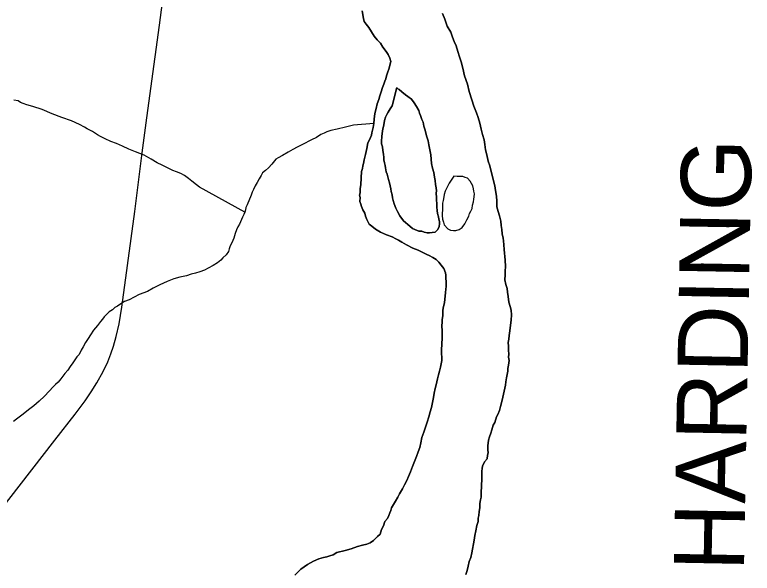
# Model space of a CAD drawing. Extents: x 0 to 34, y 0 to 22.
# Drawn here: x 25.659 to 26.257, y 15.442 to 15.894 of the extents above; entities that cross this region are included whole.
import ezdxf

# ---------------------------------------------------------------- set-up
doc = ezdxf.new("R2010")
doc.units = 0
for name, color, linetype in [('GM_X_County_Road_Text', 7, 'Continuous'), ('GM_X_Major_River', 7, 'Continuous'), ('GM_X_Minor_River', 7, 'Continuous'), ('GM_X_State_Route', 7, 'Continuous')]:
    doc.layers.add(name, color=color, linetype=linetype)

msp = doc.modelspace()

# ---------------------------------------------------------------- linework, layer by layer
at = {"layer": 'GM_X_Major_River'}
for points in [[(25.94104, 15.8974), (25.94199, 15.89128), (25.94266, 15.88859), (25.94413, 15.88664), (25.94632, 15.88391), (25.9485, 15.88041), (25.95067, 15.87691), (25.95324, 15.87379), (25.95581, 15.87104), (25.95762, 15.86794), (25.96055, 15.86441), (25.962, 15.86208), (25.96343, 15.85899), (25.9641, 15.85631), (25.96366, 15.85442), (25.96279, 15.85102), (25.96153, 15.84726), (25.96068, 15.84463), (25.96023, 15.84236), (25.95941, 15.84048), (25.95856, 15.83785), (25.95734, 15.83522), (25.95646, 15.83183), (25.95521, 15.82845), (25.95435, 15.82543), (25.9531, 15.82205), (25.95222, 15.81827), (25.95133, 15.81412), (25.9508, 15.80957), (25.95031, 15.80616), (25.94982, 15.80275), (25.94893, 15.79859), (25.94849, 15.79671), (25.94685, 15.79296), (25.94562, 15.79033), (25.94471, 15.7858), (25.94379, 15.78088), (25.94252, 15.77674), (25.94204, 15.77371), (25.9416, 15.77182), (25.94115, 15.76956), (25.94031, 15.7673), (25.93997, 15.75666), (25.93948, 15.75325), (25.93937, 15.74983), (25.93893, 15.74794), (25.93925, 15.74603), (25.93916, 15.74299), (25.93984, 15.74068), (25.94054, 15.73876), (25.9416, 15.73606), (25.94304, 15.73335), (25.94372, 15.73104), (25.94478, 15.72834), (25.94656, 15.72448), (25.9488, 15.72289), (25.95177, 15.7205), (25.95588, 15.71809), (25.96076, 15.71602), (25.96528, 15.71435), (25.96828, 15.71273), (25.97052, 15.71152), (25.97314, 15.70991), (25.97688, 15.70788), (25.98212, 15.70505), (25.98626, 15.70339), (25.99001, 15.70174), (25.99339, 15.70011), (25.99527, 15.69928)], [(25.99527, 15.69928), (25.99339, 15.70011), (25.99001, 15.70174), (25.98626, 15.70339), (25.98212, 15.70505), (25.97688, 15.70788), (25.97314, 15.70991), (25.97052, 15.71152), (25.96828, 15.71273), (25.96528, 15.71435), (25.96076, 15.71602), (25.95588, 15.71809), (25.95177, 15.7205), (25.9488, 15.72289), (25.94656, 15.72448), (25.94478, 15.72834), (25.94372, 15.73104), (25.94304, 15.73335), (25.9416, 15.73606), (25.94054, 15.73876), (25.93984, 15.74068), (25.93916, 15.74299), (25.93925, 15.74603), (25.93893, 15.74794), (25.93937, 15.74983), (25.93948, 15.75325), (25.93997, 15.75666), (25.94031, 15.7673), (25.94115, 15.76956), (25.9416, 15.77182), (25.94204, 15.77371), (25.94252, 15.77674), (25.94379, 15.78088), (25.94471, 15.7858), (25.94562, 15.79033), (25.94685, 15.79296), (25.94849, 15.79671), (25.94893, 15.79859), (25.94982, 15.80275), (25.95031, 15.80616), (25.9508, 15.80957), (25.95133, 15.81412), (25.95222, 15.81827), (25.9531, 15.82205), (25.95435, 15.82543), (25.95521, 15.82845), (25.95646, 15.83183), (25.95734, 15.83522), (25.95856, 15.83785), (25.95941, 15.84048), (25.96023, 15.84236), (25.96068, 15.84463), (25.96153, 15.84726), (25.96279, 15.85102), (25.96366, 15.85442), (25.9641, 15.85631), (25.96343, 15.85899), (25.962, 15.86208), (25.96055, 15.86441), (25.95762, 15.86794), (25.95581, 15.87104), (25.95324, 15.87379), (25.95067, 15.87691), (25.9485, 15.88041), (25.94632, 15.88391), (25.94413, 15.88664), (25.94266, 15.88859), (25.94199, 15.89128), (25.94104, 15.8974)], [(26.04543, 15.76725), (26.04443, 15.77185), (26.04303, 15.7757), (26.04205, 15.78068), (26.04104, 15.7849), (26.04041, 15.78911), (26.03977, 15.79293), (26.03838, 15.79716), (26.03738, 15.80138), (26.03639, 15.80636), (26.03502, 15.81097), (26.03361, 15.81482), (26.0315, 15.82022), (26.02976, 15.82522), (26.02769, 15.83214), (26.02635, 15.83789), (26.02391, 15.84482), (26.02258, 15.85095), (26.02122, 15.85594), (26.01983, 15.86017), (26.01844, 15.86441), (26.01707, 15.86902), (26.01565, 15.87248), (26.01424, 15.87596), (26.01285, 15.88019), (26.00995, 15.88485), (26.00785, 15.89063), (26.0061, 15.89525)], [(26.0061, 15.89525), (26.00785, 15.89063), (26.00995, 15.88485), (26.01285, 15.88019), (26.01424, 15.87596), (26.01565, 15.87248), (26.01707, 15.86902), (26.01844, 15.86441), (26.01983, 15.86017), (26.02122, 15.85594), (26.02258, 15.85095), (26.02391, 15.84482), (26.02635, 15.83789), (26.02769, 15.83214), (26.02976, 15.82522), (26.0315, 15.82022), (26.03361, 15.81482), (26.03502, 15.81097), (26.03639, 15.80636), (26.03738, 15.80138), (26.03838, 15.79716), (26.03977, 15.79293), (26.04041, 15.78911), (26.04104, 15.7849), (26.04205, 15.78068), (26.04303, 15.7757), (26.04443, 15.77185), (26.04543, 15.76725)], [(25.96914, 15.83521), (25.96524, 15.8205), (25.96364, 15.81789), (25.96203, 15.81528), (25.96083, 15.81342), (25.96, 15.81116), (25.95915, 15.80853), (25.95871, 15.80664), (25.95823, 15.80361), (25.95779, 15.80173), (25.95729, 15.79794), (25.95683, 15.79567), (25.95671, 15.79187), (25.95664, 15.78959), (25.95733, 15.78728), (25.95761, 15.78423), (25.95828, 15.78116), (25.95857, 15.77849), (25.95851, 15.77659), (25.9592, 15.77429), (25.9595, 15.77199), (25.95982, 15.77008), (25.96049, 15.76702), (25.96119, 15.76509), (25.96188, 15.76278), (25.9622, 15.76087), (25.96325, 15.75817), (25.96355, 15.7555), (25.96424, 15.7532), (25.96454, 15.7509), (25.96522, 15.74821), (25.96553, 15.74592), (25.96621, 15.74362), (25.96689, 15.74093), (25.9683, 15.73746), (25.96974, 15.73475), (25.97153, 15.73127), (25.97446, 15.72737), (25.97965, 15.72301), (25.98187, 15.72103), (25.98375, 15.72021), (25.98676, 15.71897), (25.98942, 15.71888), (25.9913, 15.71806), (25.99357, 15.7176), (25.99547, 15.71754)], [(25.96914, 15.83521), (25.96913, 15.83483), (25.971, 15.83363), (25.97322, 15.83165), (25.97619, 15.82927), (25.97805, 15.82807), (25.98102, 15.82569), (25.98322, 15.82295), (25.98503, 15.81985), (25.98683, 15.81675), (25.98752, 15.81444), (25.98822, 15.81252), (25.98927, 15.80944), (25.99033, 15.80712), (25.991, 15.80406), (25.99203, 15.80059), (25.99302, 15.796), (25.99443, 15.79215), (25.99508, 15.7887), (25.99672, 15.78066), (25.997, 15.77722), (25.99727, 15.77379), (25.99791, 15.76997), (25.99894, 15.76651), (25.99958, 15.76268), (26.00025, 15.75999), (26.00053, 15.75656), (26.00082, 15.75389), (26.00113, 15.75159), (26.00107, 15.7497), (26.00134, 15.74626), (26.00125, 15.7436), (26.00157, 15.74169), (26.00146, 15.73827), (26.00176, 15.73559), (26.00207, 15.7333), (26.00274, 15.73062), (26.00306, 15.7287), (26.00376, 15.72678), (26.0037, 15.72488), (26.00325, 15.72261), (26.00241, 15.72035), (26.00006, 15.71815), (25.99776, 15.71784), (25.99547, 15.71754), (25.99357, 15.7176), (25.9913, 15.71806), (25.98942, 15.71888), (25.98676, 15.71897), (25.98375, 15.72021), (25.98187, 15.72103), (25.97965, 15.72301), (25.97446, 15.72737), (25.97153, 15.73127), (25.96974, 15.73475), (25.9683, 15.73746), (25.96689, 15.74093), (25.96621, 15.74362), (25.96553, 15.74592), (25.96522, 15.74821), (25.96454, 15.7509), (25.96424, 15.7532), (25.96355, 15.7555), (25.96325, 15.75817), (25.9622, 15.76087), (25.96188, 15.76278), (25.96119, 15.76509), (25.96049, 15.76702), (25.95982, 15.77008), (25.9595, 15.77199), (25.9592, 15.77429), (25.95851, 15.77659), (25.95857, 15.77849), (25.95828, 15.78116), (25.95761, 15.78423), (25.95733, 15.78728), (25.95664, 15.78959), (25.95671, 15.79187), (25.95683, 15.79567), (25.95729, 15.79794), (25.95779, 15.80173), (25.95823, 15.80361), (25.95871, 15.80664), (25.95915, 15.80853), (25.96, 15.81116), (25.96083, 15.81342), (25.96203, 15.81528), (25.96364, 15.81789), (25.96524, 15.8205), (25.96914, 15.83521)], [(25.99547, 15.71754), (25.99776, 15.71784), (26.00006, 15.71815), (26.00241, 15.72035), (26.00325, 15.72261), (26.0037, 15.72488), (26.00376, 15.72678), (26.00306, 15.7287), (26.00274, 15.73062), (26.00207, 15.7333), (26.00176, 15.73559), (26.00146, 15.73827), (26.00157, 15.74169), (26.00125, 15.7436), (26.00134, 15.74626), (26.00107, 15.7497), (26.00113, 15.75159), (26.00082, 15.75389), (26.00053, 15.75656), (26.00025, 15.75999), (25.99958, 15.76268), (25.99894, 15.76651), (25.99791, 15.76997), (25.99727, 15.77379), (25.997, 15.77722), (25.99672, 15.78066), (25.99508, 15.7887), (25.99443, 15.79215), (25.99302, 15.796), (25.99203, 15.80059), (25.991, 15.80406), (25.99033, 15.80712), (25.98927, 15.80944), (25.98822, 15.81252), (25.98752, 15.81444), (25.98683, 15.81675), (25.98503, 15.81985), (25.98322, 15.82295), (25.98102, 15.82569), (25.97805, 15.82807), (25.97619, 15.82927), (25.97322, 15.83165), (25.971, 15.83363), (25.96913, 15.83483), (25.96914, 15.83521)], [(26.02509, 15.44072), (26.02596, 15.44412), (26.02684, 15.44751), (26.02772, 15.45129), (26.02897, 15.45467), (26.02985, 15.45845), (26.0317, 15.46866), (26.0322, 15.47245), (26.03308, 15.47622), (26.03398, 15.48038), (26.03485, 15.48377), (26.03493, 15.48643), (26.03539, 15.4887), (26.03586, 15.49173), (26.03634, 15.49476), (26.03645, 15.49818), (26.03693, 15.50121), (26.03738, 15.50347), (26.03746, 15.50575), (26.03753, 15.50803), (26.03764, 15.51145), (26.03772, 15.51411), (26.03781, 15.51677), (26.03789, 15.51944), (26.03798, 15.5221), (26.03805, 15.52438), (26.03812, 15.52666), (26.03856, 15.52854), (26.04019, 15.53191), (26.04218, 15.53451), (26.04266, 15.53754), (26.0431, 15.53943), (26.04279, 15.54172), (26.0429, 15.54514), (26.04296, 15.54704), (26.04343, 15.54969), (26.04427, 15.55233), (26.04513, 15.55534), (26.04598, 15.55798), (26.04724, 15.56174), (26.04845, 15.56398), (26.04974, 15.56851), (26.05094, 15.57037), (26.05219, 15.57375), (26.05305, 15.57677), (26.05391, 15.57978), (26.05482, 15.58432), (26.05703, 15.59414), (26.0575, 15.59678), (26.05799, 15.60019), (26.05846, 15.60284), (26.05892, 15.60549), (26.05899, 15.60777), (26.05946, 15.61042), (26.05996, 15.6142), (26.05967, 15.61688), (26.05974, 15.61916), (26.05947, 15.62259), (26.05956, 15.62563), (26.05928, 15.62868), (26.05975, 15.63133), (26.06022, 15.63436), (26.06073, 15.63815), (26.06125, 15.6427), (26.06176, 15.64687), (26.0619, 15.65105), (26.06164, 15.65486), (26.06098, 15.65793), (26.05994, 15.66138), (26.05933, 15.66597), (26.05868, 15.66941), (26.05839, 15.67247), (26.05735, 15.67555), (26.05671, 15.67937), (26.05684, 15.68355), (26.05694, 15.68659), (26.05706, 15.69039), (26.05684, 15.69535), (26.05656, 15.6984), (26.05626, 15.70107), (26.05598, 15.70413), (26.05572, 15.70794), (26.05543, 15.71099), (26.05513, 15.71329), (26.05448, 15.71673), (26.05421, 15.72017), (26.05355, 15.72361), (26.05328, 15.72705), (26.05228, 15.73126), (26.05124, 15.73472), (26.05022, 15.73856), (26.04999, 15.74313), (26.04974, 15.74733), (26.04913, 15.75191), (26.04849, 15.75574), (26.04543, 15.76725)], [(26.04543, 15.76725), (26.04849, 15.75574), (26.04913, 15.75191), (26.04974, 15.74733), (26.04999, 15.74313), (26.05022, 15.73856), (26.05124, 15.73472), (26.05228, 15.73126), (26.05328, 15.72705), (26.05355, 15.72361), (26.05421, 15.72017), (26.05448, 15.71673), (26.05513, 15.71329), (26.05543, 15.71099), (26.05572, 15.70794), (26.05598, 15.70413), (26.05626, 15.70107), (26.05656, 15.6984), (26.05684, 15.69535), (26.05706, 15.69039), (26.05694, 15.68659), (26.05684, 15.68355), (26.05671, 15.67937), (26.05735, 15.67555), (26.05839, 15.67247), (26.05868, 15.66941), (26.05933, 15.66597), (26.05994, 15.66138), (26.06098, 15.65793), (26.06164, 15.65486), (26.0619, 15.65105), (26.06176, 15.64687), (26.06125, 15.6427), (26.06073, 15.63815), (26.06022, 15.63436), (26.05975, 15.63133), (26.05928, 15.62868), (26.05956, 15.62563), (26.05947, 15.62259), (26.05974, 15.61916), (26.05967, 15.61688), (26.05996, 15.6142), (26.05946, 15.61042), (26.05899, 15.60777), (26.05892, 15.60549), (26.05846, 15.60284), (26.05799, 15.60019), (26.0575, 15.59678), (26.05703, 15.59414), (26.05482, 15.58432), (26.05391, 15.57978), (26.05305, 15.57677), (26.05219, 15.57375), (26.05094, 15.57037), (26.04974, 15.56851), (26.04845, 15.56398), (26.04724, 15.56174), (26.04598, 15.55798), (26.04513, 15.55534), (26.04427, 15.55233), (26.04343, 15.54969), (26.04296, 15.54704), (26.0429, 15.54514), (26.04279, 15.54172), (26.0431, 15.53943), (26.04266, 15.53754), (26.04218, 15.53451), (26.04019, 15.53191), (26.03856, 15.52854), (26.03812, 15.52666), (26.03805, 15.52438), (26.03798, 15.5221), (26.03789, 15.51944), (26.03781, 15.51677), (26.03772, 15.51411), (26.03764, 15.51145), (26.03753, 15.50803), (26.03746, 15.50575), (26.03738, 15.50347), (26.03693, 15.50121), (26.03645, 15.49818), (26.03634, 15.49476), (26.03586, 15.49173), (26.03539, 15.4887), (26.03493, 15.48643), (26.03485, 15.48377), (26.03398, 15.48038), (26.03308, 15.47622), (26.0322, 15.47245), (26.0317, 15.46866), (26.02985, 15.45845), (26.02897, 15.45467), (26.02772, 15.45129), (26.02684, 15.44751), (26.02596, 15.44412), (26.02509, 15.44072)], [(26.02206, 15.76308), (26.02016, 15.76314), (26.01787, 15.76322), (26.01521, 15.76331), (26.01362, 15.76108), (26.0116, 15.75772), (26.00958, 15.75398), (26.00836, 15.75136), (26.00751, 15.74872), (26.00707, 15.74683), (26.00659, 15.74381), (26.00614, 15.74154), (26.00602, 15.73774), (26.00596, 15.73584), (26.00588, 15.73356), (26.00582, 15.73166), (26.00611, 15.7286), (26.00679, 15.7263), (26.00748, 15.72399), (26.01043, 15.72085), (26.01268, 15.71963), (26.01496, 15.71956)], [(26.02206, 15.76308), (26.02016, 15.76314), (26.01787, 15.76322), (26.01521, 15.76331), (26.01362, 15.76108), (26.0116, 15.75772), (26.00958, 15.75398), (26.00836, 15.75136), (26.00751, 15.74872), (26.00707, 15.74683), (26.00659, 15.74381), (26.00614, 15.74154), (26.00602, 15.73774), (26.00596, 15.73584), (26.00588, 15.73356), (26.00582, 15.73166), (26.00611, 15.7286), (26.00679, 15.7263), (26.00748, 15.72399), (26.01043, 15.72085), (26.01268, 15.71963), (26.01496, 15.71956), (26.01686, 15.7195), (26.01955, 15.72017), (26.02189, 15.72199), (26.02427, 15.72496), (26.02589, 15.72795), (26.02751, 15.73094), (26.02796, 15.73321), (26.02916, 15.73507), (26.03, 15.73733), (26.03046, 15.73997), (26.03131, 15.74261), (26.03138, 15.74489), (26.03182, 15.74678), (26.03189, 15.74906), (26.03159, 15.75135), (26.03127, 15.75326), (26.03058, 15.75557), (26.02842, 15.75945), (26.02621, 15.7618), (26.02432, 15.76224), (26.02244, 15.76307), (26.02206, 15.76308)], [(26.01496, 15.71956), (26.01686, 15.7195), (26.01955, 15.72017), (26.02189, 15.72199), (26.02427, 15.72496), (26.02589, 15.72795), (26.02751, 15.73094), (26.02796, 15.73321), (26.02916, 15.73507), (26.03, 15.73733), (26.03046, 15.73997), (26.03131, 15.74261), (26.03138, 15.74489), (26.03182, 15.74678), (26.03189, 15.74906), (26.03159, 15.75135), (26.03127, 15.75326), (26.03058, 15.75557), (26.02842, 15.75945), (26.02621, 15.7618), (26.02432, 15.76224), (26.02244, 15.76307), (26.02206, 15.76308)], [(25.99527, 15.69928), (25.99826, 15.69766), (26.00088, 15.69606), (26.00309, 15.6937), (26.00492, 15.69136), (26.00711, 15.68862), (26.00853, 15.68515), (26.00885, 15.68323), (26.00875, 15.6802), (26.00907, 15.67828), (26.00901, 15.67638), (26.00893, 15.6741), (26.00886, 15.67182), (26.0084, 15.66917), (26.00775, 15.66082), (26.00689, 15.65781), (26.00641, 15.65478), (26.00634, 15.6525), (26.00628, 15.6506), (26.00579, 15.64719), (26.00573, 15.64529), (26.00563, 15.64225), (26.00588, 15.63806), (26.0057, 15.63236), (26.00554, 15.62742), (26.00539, 15.62285), (26.00528, 15.61943), (26.00558, 15.61676), (26.0055, 15.6141), (26.00503, 15.61145), (26.00457, 15.60881), (26.00369, 15.60541), (26.00284, 15.60239), (26.00198, 15.59938), (26.00106, 15.59446), (26.0002, 15.59145), (25.99932, 15.58767), (25.99883, 15.58426), (25.99794, 15.58011), (25.99704, 15.57595), (25.99617, 15.57256), (25.9949, 15.56841), (25.99362, 15.56427), (25.99235, 15.56013), (25.99107, 15.55598), (25.98942, 15.55185), (25.98851, 15.54732), (25.98763, 15.54354), (25.98638, 15.54016), (25.98511, 15.5364), (25.98346, 15.53227), (25.9818, 15.52814), (25.98015, 15.52401), (25.9785, 15.52026), (25.97725, 15.51687), (25.97524, 15.51352), (25.97361, 15.51014), (25.9712, 15.50604), (25.96997, 15.50342), (25.96796, 15.50006), (25.96475, 15.49484), (25.96429, 15.49257), (25.96347, 15.4907), (25.96264, 15.48844), (25.96142, 15.4862), (25.95943, 15.4836), (25.95818, 15.48022), (25.95657, 15.47723), (25.95568, 15.47345), (25.95334, 15.47163), (25.95019, 15.46831), (25.94746, 15.46649), (25.94476, 15.46544), (25.9413, 15.46441), (25.93708, 15.46341), (25.93208, 15.46167), (25.92708, 15.46032), (25.92055, 15.45863), (25.91745, 15.45683), (25.91475, 15.45578), (25.91244, 15.45509), (25.90975, 15.45442), (25.90592, 15.45341), (25.90167, 15.45165), (25.89663, 15.44877), (25.89118, 15.44514), (25.88645, 15.44035)], [(25.88645, 15.44035), (25.89118, 15.44514), (25.89663, 15.44877), (25.90167, 15.45165), (25.90592, 15.45341), (25.90975, 15.45442), (25.91244, 15.45509), (25.91475, 15.45578), (25.91745, 15.45683), (25.92055, 15.45863), (25.92708, 15.46032), (25.93208, 15.46167), (25.93708, 15.46341), (25.9413, 15.46441), (25.94476, 15.46544), (25.94746, 15.46649), (25.95019, 15.46831), (25.95334, 15.47163), (25.95568, 15.47345), (25.95657, 15.47723), (25.95818, 15.48022), (25.95943, 15.4836), (25.96142, 15.4862), (25.96264, 15.48844), (25.96347, 15.4907), (25.96429, 15.49257), (25.96475, 15.49484), (25.96796, 15.50006), (25.96997, 15.50342), (25.9712, 15.50604), (25.97361, 15.51014), (25.97524, 15.51352), (25.97725, 15.51687), (25.9785, 15.52026), (25.98015, 15.52401), (25.9818, 15.52814), (25.98346, 15.53227), (25.98511, 15.5364), (25.98638, 15.54016), (25.98763, 15.54354), (25.98851, 15.54732), (25.98942, 15.55185), (25.99107, 15.55598), (25.99235, 15.56013), (25.99362, 15.56427), (25.9949, 15.56841), (25.99617, 15.57256), (25.99704, 15.57595), (25.99794, 15.58011), (25.99883, 15.58426), (25.99932, 15.58767), (26.0002, 15.59145), (26.00106, 15.59446), (26.00198, 15.59938), (26.00284, 15.60239), (26.00369, 15.60541), (26.00457, 15.60881), (26.00503, 15.61145), (26.0055, 15.6141), (26.00558, 15.61676), (26.00528, 15.61943), (26.00539, 15.62285), (26.00554, 15.62742), (26.0057, 15.63236), (26.00588, 15.63806), (26.00563, 15.64225), (26.00573, 15.64529), (26.00579, 15.64719), (26.00628, 15.6506), (26.00634, 15.6525), (26.00641, 15.65478), (26.00689, 15.65781), (26.00775, 15.66082), (26.0084, 15.66917), (26.00886, 15.67182), (26.00893, 15.6741), (26.00901, 15.67638), (26.00907, 15.67828), (26.00875, 15.6802), (26.00885, 15.68323), (26.00853, 15.68515), (26.00711, 15.68862), (26.00492, 15.69136), (26.00309, 15.6937), (26.00088, 15.69606), (25.99826, 15.69766), (25.99527, 15.69928)]]:
    msp.add_lwpolyline(points, dxfattribs=at)
at = {"layer": 'GM_X_Minor_River'}
for points in [[(25.84595, 15.73427), (25.80927, 15.75451), (25.80667, 15.75649), (25.80295, 15.75928), (25.80036, 15.76165), (25.79701, 15.76404), (25.79401, 15.76566), (25.79063, 15.76692), (25.78762, 15.76816), (25.77899, 15.77225), (25.77487, 15.77429), (25.77001, 15.77711), (25.7644, 15.78034), (25.75725, 15.78324), (25.75199, 15.78531), (25.74673, 15.78777), (25.74185, 15.78983), (25.73733, 15.79151), (25.73283, 15.79356), (25.72908, 15.79558), (25.72646, 15.79681), (25.72422, 15.79841), (25.72236, 15.79961), (25.71823, 15.80165), (25.716, 15.80324), (25.71187, 15.80528), (25.70549, 15.80816), (25.69759, 15.81108), (25.68968, 15.814), (25.68179, 15.81731), (25.67425, 15.81984), (25.66935, 15.82114), (25.66634, 15.82238), (25.66408, 15.82322), (25.66221, 15.82442), (25.6588, 15.82492)], [(25.95031, 15.80616), (25.93389, 15.8048), (25.92736, 15.80311), (25.92084, 15.80143), (25.91547, 15.80046), (25.91239, 15.79942), (25.91008, 15.79836), (25.90738, 15.7973), (25.90387, 15.79476), (25.9, 15.79298), (25.89264, 15.78904), (25.88838, 15.7869), (25.8849, 15.78511), (25.88102, 15.78295), (25.87636, 15.78006), (25.87287, 15.77828), (25.87093, 15.7772), (25.86776, 15.77312), (25.865, 15.77017), (25.86264, 15.76796), (25.8603, 15.76614), (25.85908, 15.7639), (25.85748, 15.76129), (25.85586, 15.7583), (25.85425, 15.75568), (25.85301, 15.75268), (25.8518, 15.75044), (25.85096, 15.74818), (25.84767, 15.7403), (25.84683, 15.73805), (25.84639, 15.73616), (25.84595, 15.73427), (25.84513, 15.7324), (25.84391, 15.73015), (25.84309, 15.72828), (25.84227, 15.7264), (25.84145, 15.72453), (25.84024, 15.72229), (25.83902, 15.72004), (25.83816, 15.71703), (25.8369, 15.71327), (25.83526, 15.70951), (25.83403, 15.70689), (25.8332, 15.70464), (25.83275, 15.70237), (25.83076, 15.69977), (25.82801, 15.6972), (25.82643, 15.69535), (25.82369, 15.69316), (25.82019, 15.69099), (25.81632, 15.68883), (25.81322, 15.68741), (25.80937, 15.68602), (25.80591, 15.68499), (25.80245, 15.68396), (25.7986, 15.68257), (25.79323, 15.68161), (25.78824, 15.68025), (25.78284, 15.67814), (25.77704, 15.67529), (25.77163, 15.67281), (25.76696, 15.66992), (25.76041, 15.66747), (25.75615, 15.66533), (25.75228, 15.66317), (25.74842, 15.66178), (25.74532, 15.65998), (25.7426, 15.65817), (25.74066, 15.65709), (25.73869, 15.65525), (25.73597, 15.65344), (25.73203, 15.64938), (25.73045, 15.64753), (25.72887, 15.64568), (25.72647, 15.64234), (25.72331, 15.63864), (25.72091, 15.63491), (25.71891, 15.63194), (25.7169, 15.62858), (25.71489, 15.62522), (25.71328, 15.62261), (25.71164, 15.61886), (25.70967, 15.61702), (25.70807, 15.61479), (25.70647, 15.61218), (25.70447, 15.6092), (25.70247, 15.60623), (25.7001, 15.60364), (25.69851, 15.60141), (25.69691, 15.59918), (25.69455, 15.5966), (25.69258, 15.59476), (25.69062, 15.59292), (25.68746, 15.58922), (25.68352, 15.58516), (25.6792, 15.58112), (25.67489, 15.57746), (25.6706, 15.57418), (25.66629, 15.57052)], [(25.66629, 15.57052), (25.66318, 15.56834), (25.66083, 15.56651), (25.65849, 15.56469)]]:
    msp.add_lwpolyline(points, dxfattribs=at)
at = {"layer": 'GM_X_State_Route'}
msp.add_lwpolyline([(25.57313, 15.39691), (25.60896, 15.44324), (25.65464, 15.50143), (25.692, 15.54957), (25.70849, 15.57059), (25.71659, 15.58157), (25.7215, 15.58872), (25.72606, 15.59607), (25.7311, 15.6053), (25.73479, 15.61311), (25.73734, 15.61941), (25.73956, 15.62581), (25.74175, 15.63353), (25.74395, 15.64381), (25.7462, 15.65726), (25.75078, 15.69114), (25.75665, 15.73489), (25.76276, 15.78237), (25.76637, 15.81075), (25.77336, 15.86), (25.77686, 15.88586), (25.78049, 15.91483)], dxfattribs=at)

# ---------------------------------------------------------------- texts
at = {"layer": 'GM_X_County_Road_Text'}
msp.add_text('HARDING', height=0.056818, rotation=88.96073, dxfattribs=at).set_placement((26.25029, 15.44313))

doc.saveas('drawing.dxf')
